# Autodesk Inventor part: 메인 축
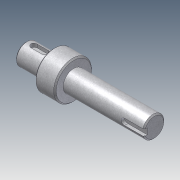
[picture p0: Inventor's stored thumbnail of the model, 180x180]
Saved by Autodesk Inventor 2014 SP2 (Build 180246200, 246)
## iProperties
Company: 한국ATC센터
Created: 2014-10
Part Number: 메인 축
Document SubType Name: Modeling
Designer: KYOUNG IL JANG
Density: 1 g/cm^3
Mass: 29.2926 g
Surface Area: 74.3518 cm^2
Volume: 29.2926 cm^3
Material: 일반
Appearance: 금속-강(스테인리스, 브러시됨)
Author: KYOUNG IL JANG
Revision Number: 1
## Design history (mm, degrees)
sketch "스케치1"
  geometry: L1 (10.497, -57.5)-(112.497, -57.5); L2 (10.497, -66)-(32.497, -66); L3 (32.497, -72.5)-(46.5, -72.5); L4 (46.5, -66)-(112.497, -66); L5 (112.497, -66)-(112.497, -57.5); L6 (10.497, -66)-(10.497, -57.5); L7 (46.5, -69.749)-(46.5, -45.251) reference; L8 (46.5, -72.5)-(46.5, -66); L9 (32.497, -72.5)-(32.497, -66); L10 (32.497, -35)-(32.497, -80) reference; 3 further points
  constraints: 16 end point, 3 point on line, 2 parallel, 2 perpendicular, 1 collinear, 1 horizontal, 1 midpoint
  dimensions: "d0" = 17 diameter of L4 L1; "d1" = 30 diameter of L3 L1; "d2" = 22 distance of L2.start L2.end; "d3" = 65.99692 distance of L4.start L4.end (derived); "d5" = 17 diameter of L2 L1; "d19" = 80 distance between parallel lines of L5 L9
revolve "회전1" sketch "스케치1" stored, may be unused: angle "d4" = 90 deg
chamfer "모따기1" distance "d6" = 1; stored, may be unused: second distance "d7" = 2, angle "d8" = 45 deg
node "작업 평면1"
sketch "스케치2"
  geometry: L1 (-11, -7.5)-(-11, 7.5) reference; L2 (-4.5, 2.5)-(4.5, 2.5); L3 (4.5, -2.5)-(-4.5, -2.5); A1 r 2.5 centre (4.5, 0) between (4.5, -2.5) and (4.5, 2.5); A2 r 2.5 centre (-4.5, 0) between (-4.5, 2.5) and (-4.5, -2.5); 2 further points
  constraints: 4 end point, 4 point on circle, 4 tangent, 2 centre point, 1 horizontal alignment, 1 midpoint, 1 parallel, 1 perpendicular
  dimensions: "d9" = 5 distance between parallel lines of L3 L2; "d10" = 14 dimension on A1 A2; "d11" = 4 distance edge to line of A2 L1
extrude "돌출1" cut sketch "스케치2" distance "d12" = 3; taper "d13" = 0 deg
node "작업 평면2"
sketch "스케치3"
  geometry: L1 (32.998, 7.5)-(32.998, -7.5) reference; L2 (32.998, 2.5)-(17.498, 2.5); L3 (17.498, -2.5)-(32.998, -2.5); A1 r 2.5 centre (17.498, 0) between (17.498, 2.5) and (17.498, -2.5); 2 further points
  constraints: 4 end point, 2 perpendicular, 2 point on circle, 2 point on line, 2 tangent, 1 centre point, 1 horizontal alignment, 1 midpoint
  dimensions: "d14" = 5 distance between parallel lines of L3 L2; "d15" = 18 dimension on A1 L1
extrude "돌출2" cut sketch "스케치3" distance "d16" = 3; taper "d17" = 0 deg
node "솔리드1"
node "참조4"
node "참조5"
